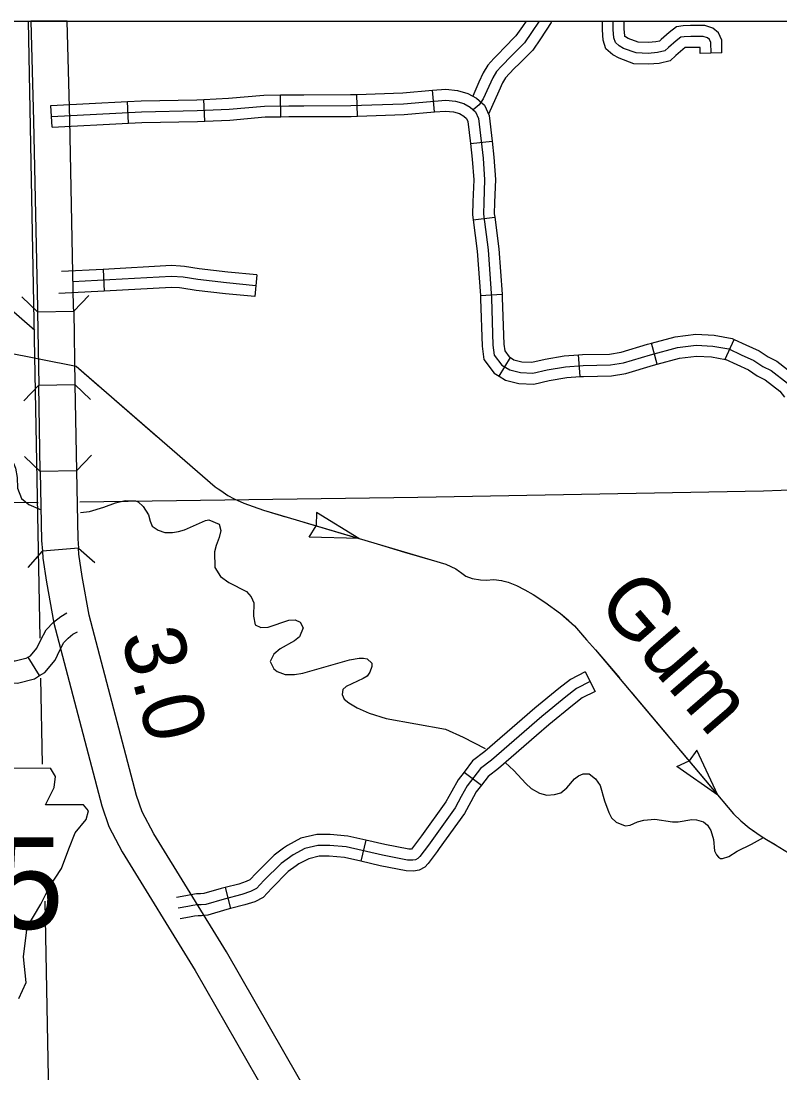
# Model space of a CAD drawing. Extents: x 1374139 to 1377472, y 1168351 to 1170484.
# Drawn here: x 1376444.7 to 1376549.4, y 1169434.3 to 1169579.4 of the extents above; entities that cross this region are included whole.
import ezdxf

# ---------------------------------------------------------------- set-up
doc = ezdxf.new("R2010")
doc.units = 0
doc.layers.add('26', color=7, linetype='Continuous')
doc.layers.add('Default', color=7, linetype='Continuous')

msp = doc.modelspace()

# ---------------------------------------------------------------- linework, layer by layer
at = {"layer": '26'}
msp.add_lwpolyline([(1375090, 1169579.43), (1376597.43, 1169579.43), (1376597.43, 1168653.79), (1375090, 1168653.79)], close=True, dxfattribs=at)
at = {"layer": 'Default'}
for p, q in [((1376451.03, 1169579.43), (1376446.03, 1169579.43)), ((1376446.03, 1169579.43), (1376446.39, 1169565.65)), ((1376451.38, 1169565.77), (1376451.03, 1169579.43)), ((1376541.44, 1169575.03), (1376538.44, 1169574.97)), ((1376480.53, 1169566.22), (1376480.49, 1169569.22)), ((1376491.12, 1169566.3), (1376491.02, 1169569.3)), ((1376501.74, 1169566.88), (1376501.48, 1169569.87)), ((1376448.95, 1169564.78), (1376448.79, 1169567.77)), ((1376459.49, 1169565.31), (1376459.34, 1169568.31)), ((1376470.04, 1169565.61), (1376469.91, 1169568.61)), ((1376446.39, 1169565.65), (1376446.92, 1169539.86)), ((1376451.92, 1169539.97), (1376451.38, 1169565.77)), ((1376506.72, 1169562.52), (1376509.7, 1169562.86)), ((1376507.1, 1169551.97), (1376510.07, 1169552.35)), ((1376455.98, 1169545.15), (1376456.14, 1169542.16)), ((1376477.23, 1169544.39), (1376476.95, 1169541.41)), ((1376508.08, 1169541.54), (1376511.07, 1169541.75)), ((1376446.92, 1169539.86), (1376446.93, 1169539.3)), ((1376446.93, 1169539.3), (1376451.93, 1169539.39)), ((1376451.93, 1169539.39), (1376451.92, 1169539.97)), ((1376532.51, 1169532.07), (1376531.73, 1169534.96)), ((1376541.87, 1169532.75), (1376543.12, 1169535.48)), ((1376510.68, 1169530.4), (1376512.23, 1169532.97)), ((1376521.88, 1169530.36), (1376521.65, 1169533.35)), ((1376447.11, 1169529.19), (1376452.11, 1169529.28)), ((1376452.32, 1169517.35), (1376447.32, 1169517.26)), ((1376485.44, 1169511.6), (1376485.39, 1169509.78)), ((1376491.29, 1169508.02), (1376485.44, 1169511.6)), ((1376484.43, 1169508.19), (1376485.39, 1169509.75)), ((1376491.29, 1169508.02), (1376484.43, 1169508.19)), ((1376452.59, 1169506.66), (1376447.61, 1169506.27)), ((1376447.23, 1169489.09), (1376445.64, 1169491.64)), ((1376522.55, 1169489.6), (1376523.91, 1169486.92)), ((1376537.95, 1169478.82), (1376536.9, 1169477.33)), ((1376540.86, 1169472.6), (1376537.95, 1169478.82)), ((1376449.41, 1169475.17), (1376448.71, 1169476.34)), ((1376535.23, 1169476.54), (1376536.89, 1169477.31)), ((1376540.86, 1169472.6), (1376535.23, 1169476.54)), ((1376449.24, 1169473.64), (1376449.41, 1169475.17)), ((1376505.84, 1169475.78), (1376508.22, 1169473.96)), ((1376448.06, 1169471.27), (1376449.24, 1169473.64)), ((1376453.3, 1169471.27), (1376448.06, 1169471.27)), ((1376453.98, 1169470.43), (1376453.3, 1169471.27)), ((1376452.12, 1169467.38), (1376453.64, 1169469.24)), ((1376453.64, 1169469.24), (1376453.98, 1169470.43)), ((1376451.27, 1169465.18), (1376452.12, 1169467.38)), ((1376492.25, 1169466.38), (1376491.57, 1169463.46)), ((1376450.26, 1169462.48), (1376451.27, 1169465.18)), ((1376448.57, 1169459.94), (1376450.26, 1169462.48)), ((1376447.38, 1169457.57), (1376448.57, 1169459.94)), ((1376472.83, 1169459.83), (1376473.58, 1169456.93)), ((1376445.52, 1169454.36), (1376447.38, 1169457.57)), ((1376445.01, 1169450.3), (1376445.52, 1169454.36)), ((1376445.35, 1169446.74), (1376445.01, 1169450.3)), ((1376444.34, 1169444.54), (1376445.35, 1169446.74))]:
    msp.add_line(p, q, dxfattribs=at)
for points in [[(1376445.65, 1169579.43), (1376447.26, 1169494.26)], [(1376516.19, 1169579.43), (1376515.15, 1169577.83), (1376514.16, 1169576.4), (1376512.4, 1169574.64), (1376511.01, 1169573.22), (1376510.31, 1169572.46), (1376509.82, 1169571.6), (1376509.25, 1169570.37), (1376508.49, 1169568.68), (1376507.9, 1169567.88), (1376507.11, 1169567.16)], [(1376514.4, 1169579.43), (1376513.91, 1169578.66), (1376513, 1169577.37), (1376511.33, 1169575.7), (1376510.62, 1169574.96)], [(1376517.97, 1169579.43), (1376517.85, 1169579.23), (1376516.39, 1169576.99), (1376515.31, 1169575.43), (1376513.47, 1169573.59), (1376512.76, 1169572.87)], [(1376532.04, 1169573.52), (1376531.3, 1169573.46), (1376529.28, 1169573.54), (1376527.23, 1169574.29), (1376526.39, 1169574.76), (1376525.42, 1169575.61), (1376525.05, 1169576.8), (1376524.93, 1169578.23), (1376524.94, 1169579.43)], [(1376539.94, 1169575), (1376539.91, 1169576.46), (1376539.74, 1169576.86), (1376539.45, 1169577.09), (1376538.85, 1169577.29), (1376538.25, 1169577.29), (1376537.13, 1169577.29), (1376536.2, 1169577.25), (1376535.77, 1169577.19), (1376535.11, 1169576.69), (1376534.05, 1169575.76), (1376533.55, 1169575.3), (1376532.52, 1169575.07), (1376531.27, 1169574.97), (1376529.58, 1169575.03), (1376527.85, 1169575.66), (1376527.26, 1169575.99), (1376526.73, 1169576.46), (1376526.53, 1169577.09), (1376526.43, 1169578.28), (1376526.44, 1169579.43)], [(1376531.8, 1169576.51), (1376531.24, 1169576.47), (1376529.87, 1169576.52), (1376528.48, 1169577.03), (1376528.13, 1169577.23), (1376528.03, 1169577.31), (1376528.01, 1169577.38), (1376527.93, 1169578.33), (1376527.94, 1169579.43)], [(1376541.44, 1169575.03), (1376541.4, 1169576.77), (1376540.98, 1169577.8), (1376540.17, 1169578.43), (1376539.09, 1169578.79), (1376538.25, 1169578.79), (1376537.1, 1169578.79), (1376536.06, 1169578.75), (1376535.17, 1169578.61), (1376534.16, 1169577.86), (1376533.04, 1169576.87), (1376532.82, 1169576.67), (1376532.3, 1169576.55), (1376531.8, 1169576.51)], [(1376538.44, 1169574.97), (1376538.43, 1169575.79), (1376538.25, 1169575.79), (1376537.16, 1169575.79), (1376536.37, 1169575.76), (1376536.05, 1169575.52), (1376535.05, 1169574.65), (1376534.28, 1169573.92), (1376532.75, 1169573.58), (1376532.04, 1169573.52)], [(1376510.62, 1169574.96), (1376509.92, 1169574.25), (1376509.1, 1169573.35), (1376508.48, 1169572.29), (1376507.89, 1169570.99), (1376507.02, 1169569.07)], [(1376512.76, 1169572.87), (1376512.1, 1169572.19), (1376511.53, 1169571.57), (1376511.15, 1169570.91), (1376510.62, 1169569.75), (1376509.2, 1169566.59)], [(1376469.91, 1169568.61), (1376473.29, 1169568.76), (1376478.2, 1169569.19), (1376480.49, 1169569.22)], [(1376480.49, 1169569.22), (1376481.61, 1169569.23), (1376483.69, 1169569.23), (1376490.17, 1169569.27), (1376491.02, 1169569.3)], [(1376491.02, 1169569.3), (1376497.38, 1169569.51), (1376501.48, 1169569.87)], [(1376501.48, 1169569.87), (1376503.33, 1169570.03), (1376504.93, 1169569.84), (1376506.37, 1169569.44), (1376507.57, 1169568.76), (1376508.64, 1169567.82), (1376509.3, 1169566.37), (1376509.7, 1169562.86)], [(1376448.79, 1169567.77), (1376459.34, 1169568.31)], [(1376448.87, 1169566.27), (1376461.29, 1169566.9), (1376468.97, 1169567.06), (1376473.39, 1169567.26), (1376478.27, 1169567.69), (1376481.62, 1169567.73), (1376483.69, 1169567.73), (1376490.2, 1169567.77), (1376497.47, 1169568.01), (1376503.31, 1169568.52), (1376504.65, 1169568.36), (1376505.79, 1169568.05), (1376506.69, 1169567.54), (1376507.4, 1169566.9), (1376507.84, 1169565.96), (1376508.47, 1169560.49), (1376508.67, 1169557.53), (1376508.55, 1169554.42), (1376508.51, 1169552.76), (1376509.14, 1169547.83), (1376509.61, 1169541.17), (1376509.81, 1169534.7), (1376510, 1169533.32), (1376511.03, 1169531.94), (1376512.13, 1169531.27), (1376513.6, 1169530.9), (1376515.34, 1169530.84), (1376517.3, 1169531.27), (1376519.82, 1169531.71), (1376522.27, 1169531.89), (1376526.03, 1169531.97), (1376527.83, 1169532.25), (1376531.59, 1169533.37), (1376535.29, 1169534.37), (1376537.89, 1169534.68), (1376540.17, 1169534.56), (1376542.38, 1169534.17), (1376544.11, 1169533.38), (1376545.85, 1169532.6), (1376547.07, 1169531.77), (1376548.21, 1169531.21), (1376550.5, 1169529.44)], [(1376459.34, 1169568.31), (1376461.23, 1169568.4), (1376468.92, 1169568.56), (1376469.91, 1169568.61)], [(1376480.53, 1169566.22), (1376481.63, 1169566.23), (1376483.7, 1169566.23), (1376490.23, 1169566.27), (1376491.12, 1169566.3)], [(1376491.12, 1169566.3), (1376497.56, 1169566.51), (1376501.74, 1169566.88)], [(1376501.74, 1169566.88), (1376503.28, 1169567.01), (1376504.36, 1169566.89), (1376505.21, 1169566.65), (1376505.82, 1169566.31), (1376506.17, 1169565.99), (1376506.37, 1169565.55), (1376506.72, 1169562.52)], [(1376448.95, 1169564.78), (1376459.49, 1169565.31)], [(1376459.49, 1169565.31), (1376461.34, 1169565.41), (1376469.02, 1169565.56), (1376470.04, 1169565.61)], [(1376470.04, 1169565.61), (1376473.49, 1169565.76), (1376478.35, 1169566.19), (1376480.53, 1169566.22)], [(1376506.72, 1169562.52), (1376506.97, 1169560.35), (1376507.16, 1169557.51), (1376507.05, 1169554.46), (1376507.01, 1169552.68), (1376507.1, 1169551.97)], [(1376509.7, 1169562.86), (1376509.96, 1169560.63), (1376510.17, 1169557.55), (1376510.05, 1169554.37), (1376510.01, 1169552.84), (1376510.07, 1169552.35)], [(1376507.1, 1169551.97), (1376507.64, 1169547.68), (1376508.08, 1169541.54)], [(1376510.07, 1169552.35), (1376510.63, 1169547.98), (1376511.07, 1169541.75)], [(1376433.59, 1169548.03), (1376446.57, 1169536.75)], [(1376455.98, 1169545.15), (1376450.26, 1169544.84)], [(1376466.69, 1169545.6), (1376465.45, 1169545.67), (1376455.98, 1169545.15)], [(1376477.23, 1169544.39), (1376473.21, 1169544.77), (1376469.27, 1169545.23), (1376467.21, 1169545.57), (1376466.69, 1169545.6)], [(1376477.09, 1169542.9), (1376473.05, 1169543.28), (1376469.06, 1169543.75), (1376467.04, 1169544.08), (1376465.45, 1169544.17), (1376451.8, 1169543.42)], [(1376456.14, 1169542.16), (1376449.87, 1169541.82)], [(1376466.52, 1169542.6), (1376465.44, 1169542.67), (1376456.14, 1169542.16)], [(1376476.95, 1169541.41), (1376472.9, 1169541.78), (1376468.85, 1169542.26), (1376466.88, 1169542.58), (1376466.52, 1169542.6)], [(1376511.07, 1169541.75), (1376511.11, 1169541.25), (1376511.3, 1169534.83), (1376511.44, 1169533.91), (1376512.06, 1169533.07), (1376512.23, 1169532.97)], [(1376446.93, 1169539.3), (1376444.77, 1169541.38)], [(1376454.01, 1169541.55), (1376451.93, 1169539.39)], [(1376508.08, 1169541.54), (1376508.11, 1169541.09), (1376508.31, 1169534.57), (1376508.57, 1169532.73), (1376510, 1169530.81), (1376510.68, 1169530.4)], [(1376446.93, 1169539.3), (1376447.11, 1169529.19)], [(1376451.93, 1169539.39), (1376452.11, 1169529.28)], [(1376446.54, 1169536.78), (1376446.57, 1169536.75)], [(1376531.73, 1169534.96), (1376535, 1169535.84), (1376537.84, 1169536.19), (1376540.34, 1169536.06), (1376542.83, 1169535.61), (1376543.12, 1169535.48)], [(1376521.65, 1169533.35), (1376522.2, 1169533.39), (1376525.9, 1169533.47), (1376527.5, 1169533.72), (1376531.18, 1169534.82), (1376531.73, 1169534.96)], [(1376543.12, 1169535.48), (1376544.73, 1169534.75), (1376546.58, 1169533.91), (1376547.82, 1169533.07), (1376549.01, 1169532.5), (1376551.56, 1169530.51), (1376552.44, 1169529.41)], [(1376442.3, 1169533.76), (1376452.26, 1169531.81), (1376471.46, 1169515.13), (1376471.88, 1169514.86), (1376472.23, 1169514.62), (1376473.22, 1169513.94), (1376474.07, 1169513.48), (1376475.44, 1169512.87), (1376476.69, 1169512.41), (1376478.12, 1169511.92), (1376503.3, 1169504.46), (1376504.69, 1169503.83), (1376505.2, 1169503.48), (1376505.34, 1169503.38), (1376506.07, 1169502.83), (1376506.94, 1169502.49), (1376508.08, 1169502.33), (1376508.88, 1169502.25), (1376509.94, 1169502.35), (1376510.98, 1169502.23), (1376511.9, 1169501.97), (1376513.05, 1169501.53), (1376514.24, 1169500.93), (1376515.37, 1169500.29), (1376516.99, 1169499.24), (1376519.16, 1169497.66), (1376521.09, 1169495.98), (1376522.75, 1169494.03), (1376523.99, 1169492.67), (1376543.03, 1169470.01), (1376544.05, 1169469.05), (1376545.21, 1169468.07), (1376546.71, 1169467.04), (1376547.6, 1169466.48), (1376548.85, 1169465.76), (1376550.63, 1169464.62)], [(1376512.23, 1169532.97), (1376512.72, 1169532.67), (1376513.82, 1169532.4), (1376515.21, 1169532.34), (1376517.01, 1169532.74), (1376519.63, 1169533.2), (1376521.65, 1169533.35)], [(1376532.51, 1169532.07), (1376535.57, 1169532.89), (1376537.94, 1169533.18), (1376540, 1169533.07), (1376541.93, 1169532.73), (1376541.87, 1169532.75)], [(1376452.26, 1169531.81), (1376455.56, 1169528.95)], [(1376521.88, 1169530.36), (1376522.34, 1169530.39), (1376526.17, 1169530.47), (1376528.16, 1169530.78), (1376532, 1169531.93), (1376532.51, 1169532.07)], [(1376541.87, 1169532.75), (1376543.5, 1169532.02), (1376545.11, 1169531.29), (1376546.32, 1169530.46), (1376547.42, 1169529.93), (1376549.44, 1169528.36), (1376550.09, 1169527.54)], [(1376510.68, 1169530.4), (1376511.55, 1169529.87), (1376513.39, 1169529.41), (1376515.48, 1169529.33), (1376517.59, 1169529.8), (1376520, 1169530.22), (1376521.88, 1169530.36)], [(1376445.03, 1169527.03), (1376447.11, 1169529.19)], [(1376447.32, 1169517.26), (1376447.11, 1169529.19)], [(1376452.11, 1169529.28), (1376454.27, 1169527.19)], [(1376452.11, 1169529.28), (1376452.32, 1169517.35)], [(1376457.55, 1169527.21), (1376463.53, 1169522.02)], [(1376431.93, 1169521.85), (1376434.52, 1169521.16), (1376434.92, 1169520.79), (1376435.45, 1169519.6), (1376435.84, 1169519.02), (1376437.26, 1169518.73), (1376439.78, 1169519.58), (1376441.26, 1169519.81), (1376442.46, 1169519.59), (1376443.37, 1169518.97), (1376443.9, 1169517.7), (1376444.14, 1169516.44), (1376444.17, 1169514.96), (1376444.72, 1169513.55), (1376445.73, 1169512.71), (1376447.42, 1169511.95)], [(1376465.52, 1169520.29), (1376471.46, 1169515.13), (1376471.51, 1169515.1)], [(1376447.32, 1169517.26), (1376445.16, 1169519.34)], [(1376454.4, 1169519.51), (1376452.32, 1169517.35)], [(1376447.32, 1169517.26), (1376447.49, 1169507.76), (1376447.61, 1169506.27)], [(1376452.32, 1169517.35), (1376452.49, 1169507.99), (1376452.59, 1169506.66)], [(1376452.76, 1169513.08), (1376499.44, 1169513.73), (1376547.18, 1169514.57), (1376552.07, 1169514.76)], [(1376421.7, 1169513.03), (1376446.91, 1169513)], [(1376446.91, 1169513), (1376447.05, 1169513)], [(1376452.86, 1169511.62), (1376452.86, 1169511.62), (1376454.1, 1169511.76), (1376456.09, 1169512.32), (1376457.71, 1169512.94), (1376459.06, 1169513.26), (1376460.46, 1169513.21), (1376460.83, 1169513.06), (1376461.52, 1169512.43), (1376462.28, 1169511.26), (1376462.48, 1169510.39), (1376462.79, 1169509.73), (1376463.6, 1169509.15), (1376464.53, 1169508.86), (1376465.58, 1169508.85), (1376466.4, 1169508.98), (1376467.24, 1169509.22), (1376470.15, 1169510.5), (1376470.59, 1169510.57), (1376472.02, 1169509.99), (1376472.23, 1169509.12), (1376472.03, 1169508.15), (1376471.59, 1169507.06), (1376471.37, 1169506.16), (1376471.43, 1169503.99), (1376472.22, 1169502.77), (1376473.37, 1169501.93), (1376475.77, 1169500.69), (1376476.43, 1169499.97), (1376476.82, 1169499.13), (1376476.76, 1169497.29), (1376476.98, 1169496.09), (1376477.77, 1169495.73), (1376478.79, 1169495.79), (1376481.63, 1169496.74), (1376482.52, 1169496.78), (1376483.21, 1169496.47), (1376483.6, 1169495.68), (1376483.11, 1169494.45), (1376482.44, 1169493.9), (1376480.44, 1169492.79)], [(1376473.72, 1169513.67), (1376474.07, 1169513.48), (1376475.44, 1169512.87), (1376476.69, 1169512.41), (1376478.12, 1169511.92), (1376481.17, 1169511.01)], [(1376483.7, 1169510.26), (1376491.29, 1169508.02)], [(1376493.83, 1169507.27), (1376497.62, 1169506.14)], [(1376445.65, 1169504), (1376447.61, 1169506.27)], [(1376447.61, 1169506.27), (1376447.68, 1169505.29), (1376448.17, 1169501.97), (1376449.18, 1169496.35), (1376455.82, 1169471.1), (1376456.8, 1169468.28), (1376458.64, 1169464.79), (1376468.72, 1169448.41), (1376484.39, 1169421.08), (1376486.77, 1169415.91), (1376487.45, 1169413.88), (1376489.8, 1169407.5), (1376498.05, 1169382.32), (1376498.84, 1169379.65), (1376499.27, 1169376.85), (1376499.4, 1169360.18)], [(1376452.59, 1169506.66), (1376454.87, 1169504.7)], [(1376504.4, 1169359.99), (1376504.27, 1169377.25), (1376503.74, 1169380.75), (1376502.82, 1169383.82), (1376494.52, 1169409.14), (1376492.17, 1169415.53), (1376491.42, 1169417.76), (1376488.84, 1169423.37), (1376473.02, 1169450.97), (1376462.99, 1169467.27), (1376461.4, 1169470.28), (1376460.61, 1169472.56), (1376454.07, 1169497.43), (1376453.11, 1169502.78), (1376452.65, 1169505.85), (1376452.59, 1169506.66)], [(1376497.62, 1169506.14), (1376501.42, 1169505.02)], [(1376503.92, 1169504.18), (1376504.69, 1169503.83), (1376505.2, 1169503.48), (1376505.34, 1169503.38), (1376506.07, 1169502.83), (1376506.94, 1169502.49), (1376508.08, 1169502.33), (1376508.88, 1169502.25), (1376509.94, 1169502.35), (1376510.98, 1169502.23), (1376511.33, 1169502.13)], [(1376513.78, 1169501.16), (1376514.24, 1169500.93), (1376515.37, 1169500.29), (1376516.99, 1169499.24), (1376519.16, 1169497.66), (1376520.29, 1169496.68)], [(1376445.64, 1169491.64), (1376445.95, 1169491.83), (1376446.85, 1169492.87), (1376447.35, 1169493.93), (1376448.13, 1169495.42), (1376449.14, 1169496.47), (1376450.14, 1169497.27), (1376451, 1169497.76)], [(1376447.23, 1169489.09), (1376447.93, 1169489.53), (1376449.39, 1169491.22), (1376450.04, 1169492.59), (1376450.59, 1169493.65), (1376451.17, 1169494.25), (1376451.83, 1169494.79), (1376452.48, 1169495.15)], [(1376445.64, 1169491.64), (1376445.33, 1169491.44), (1376443.84, 1169491.07), (1376442.63, 1169491.09), (1376441.27, 1169491.38), (1376440.41, 1169492.02), (1376438.65, 1169494.19)], [(1376522.11, 1169494.78), (1376522.75, 1169494.03), (1376523.99, 1169492.67), (1376527.27, 1169488.77)], [(1376436.32, 1169492.3), (1376438.32, 1169489.85), (1376440.01, 1169488.58), (1376442.28, 1169488.1), (1376444.18, 1169488.06), (1376446.52, 1169488.65), (1376447.23, 1169489.09)], [(1376480.44, 1169492.79), (1376479.56, 1169492.04), (1376479.06, 1169491.02), (1376479.56, 1169490.01), (1376480.02, 1169489.64), (1376481.15, 1169489.24), (1376482.43, 1169489.25), (1376483.58, 1169489.45), (1376490, 1169491.28), (1376491.34, 1169491.51), (1376491.96, 1169491.52), (1376492.46, 1169491.39), (1376493.09, 1169490.82), (1376493.08, 1169490.36), (1376492.83, 1169489.55), (1376492.47, 1169489.03), (1376491.89, 1169488.67), (1376489.55, 1169487.61), (1376489.08, 1169487.16), (1376489, 1169486.47), (1376489.27, 1169485.84), (1376489.92, 1169485.35), (1376491.05, 1169484.65), (1376492.72, 1169483.9), (1376495.08, 1169483.19), (1376503.28, 1169481.69), (1376505.7, 1169480.59), (1376508.75, 1169479.02)], [(1376522.55, 1169489.6), (1376520.54, 1169488.57), (1376518.92, 1169487.32), (1376515.62, 1169484.61), (1376513.84, 1169483.07)], [(1376447.36, 1169488.76), (1376447.59, 1169476.86)], [(1376523.23, 1169488.26), (1376521.35, 1169487.3), (1376519.86, 1169486.14), (1376516.58, 1169483.46), (1376509.64, 1169477.44), (1376508.08, 1169476.25), (1376506.27, 1169473.87), (1376505.44, 1169472.41), (1376504.61, 1169470.86), (1376500.91, 1169465.7), (1376499.72, 1169464.14), (1376499.47, 1169463.86), (1376499.12, 1169463.68), (1376498.75, 1169463.61), (1376498.03, 1169463.64), (1376494.56, 1169464.31), (1376489.56, 1169465.46), (1376487.28, 1169465.66), (1376485.66, 1169465.66), (1376483.84, 1169465.23), (1376482.22, 1169464.37), (1376480.57, 1169463.18), (1376478.19, 1169460.8), (1376477.16, 1169459.71), (1376476.34, 1169459.28), (1376475.15, 1169458.88), (1376472.7, 1169458.25), (1376470.19, 1169457.52), (1376469.52, 1169457.46), (1376468.99, 1169457.46), (1376468.37, 1169457.36), (1376467.67, 1169457.23), (1376466.37, 1169457)], [(1376523.91, 1169486.92), (1376522.15, 1169486.03), (1376520.79, 1169484.97), (1376517.55, 1169482.32), (1376515.81, 1169480.81)], [(1376528.97, 1169486.75), (1376534.06, 1169480.69)], [(1376513.84, 1169483.07), (1376508.69, 1169478.6), (1376507.01, 1169477.32), (1376505.84, 1169475.78)], [(1376515.81, 1169480.81), (1376510.59, 1169476.28), (1376509.16, 1169475.18), (1376508.22, 1169473.96)], [(1376535.76, 1169478.67), (1376540.86, 1169472.6)], [(1376418.28, 1169476.35), (1376448.71, 1169476.34)], [(1376511.52, 1169477.09), (1376512.71, 1169475.99), (1376514.37, 1169474.18), (1376515.1, 1169473.53), (1376516.23, 1169472.89), (1376517.27, 1169472.61), (1376518.31, 1169472.67), (1376519.17, 1169472.91), (1376520.03, 1169473.59), (1376521.09, 1169474.83), (1376521.64, 1169475.24), (1376522.27, 1169475.53), (1376523.09, 1169475.55), (1376524, 1169474.85), (1376524.6, 1169473.94), (1376525.24, 1169471.81), (1376525.83, 1169470.22), (1376526.19, 1169469.48), (1376526.82, 1169468.85), (1376528.09, 1169468.36), (1376528.78, 1169468.47), (1376529.77, 1169468.89), (1376530.63, 1169469.13), (1376532.19, 1169469.3), (1376534.63, 1169468.91), (1376535.41, 1169468.9), (1376537.3, 1169469.22), (1376537.92, 1169469.21), (1376538.89, 1169468.91), (1376539.42, 1169468.46), (1376539.91, 1169467.73), (1376540.27, 1169466.49), (1376540.42, 1169464.92), (1376540.67, 1169464.34), (1376540.94, 1169464.02), (1376541.24, 1169463.85), (1376541.5, 1169463.84), (1376542.4, 1169464.11), (1376543.56, 1169464.86), (1376545.5, 1169465.84), (1376547.19, 1169466.73)], [(1376505.84, 1169475.78), (1376505.01, 1169474.7), (1376504.12, 1169473.14), (1376503.33, 1169471.65), (1376499.97, 1169466.97)], [(1376508.22, 1169473.96), (1376507.52, 1169473.04), (1376506.75, 1169471.69), (1376505.89, 1169470.06), (1376502.41, 1169465.22)], [(1376542.55, 1169470.58), (1376543.03, 1169470.01), (1376544.05, 1169469.05), (1376545.21, 1169468.07), (1376545.46, 1169467.9)], [(1376545.46, 1169467.9), (1376546.71, 1169467.04), (1376547.6, 1169466.48), (1376548.8, 1169465.79)], [(1376492.25, 1169466.38), (1376489.8, 1169466.95), (1376487.35, 1169467.16), (1376485.49, 1169467.16), (1376483.31, 1169466.65), (1376481.43, 1169465.65), (1376480.91, 1169465.28)], [(1376499.97, 1169466.97), (1376499.7, 1169466.59), (1376498.58, 1169465.12), (1376498.21, 1169465.14), (1376494.87, 1169465.77), (1376492.25, 1169466.38)], [(1376480.91, 1169465.28), (1376479.59, 1169464.33), (1376477.11, 1169461.84), (1376476.24, 1169460.92), (1376475.75, 1169460.66), (1376474.72, 1169460.32), (1376472.83, 1169459.83)], [(1376502.41, 1169465.22), (1376502.11, 1169464.8), (1376500.87, 1169463.18), (1376500.4, 1169462.67), (1376499.63, 1169462.25), (1376498.85, 1169462.1), (1376497.85, 1169462.15), (1376494.25, 1169462.84), (1376491.57, 1169463.46)], [(1376491.57, 1169463.46), (1376489.33, 1169463.98), (1376487.22, 1169464.16), (1376485.84, 1169464.16), (1376484.38, 1169463.82), (1376483.02, 1169463.1), (1376482.67, 1169462.84)], [(1376482.67, 1169462.84), (1376481.54, 1169462.04), (1376479.27, 1169459.76), (1376478.08, 1169458.49), (1376476.92, 1169457.89), (1376475.57, 1169457.44), (1376473.58, 1169456.93)], [(1376472.83, 1169459.83), (1376472.3, 1169459.7), (1376469.9, 1169459), (1376469.45, 1169458.96), (1376468.88, 1169458.96), (1376468.11, 1169458.84), (1376467.4, 1169458.7), (1376466.11, 1169458.47)], [(1376447.94, 1169457.98), (1376448.91, 1169406.94)], [(1376473.58, 1169456.93), (1376473.09, 1169456.8), (1376470.47, 1169456.04), (1376469.6, 1169455.96), (1376469.11, 1169455.96), (1376468.62, 1169455.88), (1376467.94, 1169455.75), (1376466.64, 1169455.52)]]:
    msp.add_lwpolyline(points, dxfattribs=at)

# ---------------------------------------------------------------- texts
for s, rotation, p in [('Gum', 310.8078, (1376523.93, 1169498.93)), ('3.0', 284.7258, (1376458.42, 1169494.53))]:
    msp.add_text(s, height=8.448, rotation=rotation, dxfattribs=at).set_placement(p)
msp.add_text('105', height=12.672, dxfattribs=at).set_placement((1376422.26, 1169454.12))

doc.saveas('drawing.dxf')
